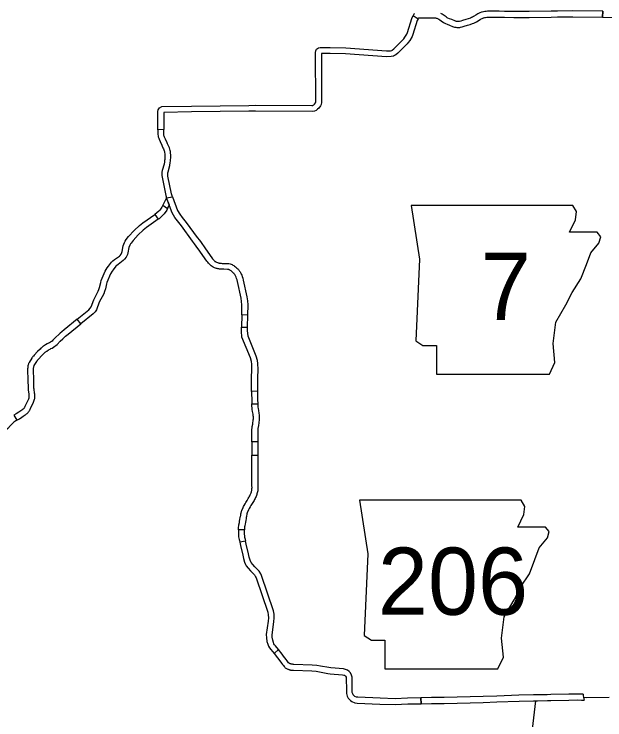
# Model space of a CAD drawing. Extents: x 77230 to 630905, y 790554 to 1662844.
# Drawn here: x 528426 to 553467, y 1510846 to 1540788 of the extents above; entities that cross this region are included whole.
import ezdxf

# ---------------------------------------------------------------- set-up
doc = ezdxf.new("R2010")
doc.units = 0
for name, color, linetype in [('Level 10', 7, 'Continuous'), ('Level 24', 7, 'Continuous'), ('Level 41', 7, 'Continuous')]:
    doc.layers.add(name, color=color, linetype=linetype)

msp = doc.modelspace()

# ---------------------------------------------------------------- linework, layer by layer
at = {"layer": 'Level 10'}
msp.add_line((539787, 1513639), (539632, 1513831), dxfattribs=at)
for points in [[(553376, 1540913), (553372, 1540663), (554654, 1540645), (556930, 1540667), (557078, 1540724), (557133, 1540754), (557189, 1540803), (557224, 1540843), (557250, 1540888), (557277, 1540964), (557289, 1541026), (557309, 1542253), (557309, 1543120), (557302, 1543626), (557052, 1543626)], [(553372, 1540663), (553376, 1540913), (552103, 1540922), (551457, 1540919), (551188, 1540910), (550258, 1540897), (549906, 1540893), (549617, 1540893), (549218, 1540903), (548984, 1540910), (548632, 1540915), (548564, 1540912), (548490, 1540910), (548431, 1540904), (548373, 1540897), (548323, 1540887), (548271, 1540873), (548244, 1540864), (548171, 1540837), (548084, 1540796)], [(541203, 1539162), (541211, 1539234), (541250, 1539306), (541325, 1539357), (541399, 1539373), (541824, 1539373), (542485, 1539357), (544207, 1539225), (544379, 1539234), (544430, 1539246), (544432, 1539246), (544457, 1539264), (544520, 1539318), (544840, 1539641), (544902, 1539699), (544940, 1539741), (544990, 1539807), (545067, 1539942), (545095, 1540011), (545282, 1540609), (545341, 1540734), (545549, 1540595)], [(545549, 1540595), (545516, 1540520), (545330, 1539928), (545293, 1539834), (545199, 1539669), (545134, 1539582), (545081, 1539523), (545014, 1539461), (544690, 1539134), (544610, 1539065), (544552, 1539026), (544507, 1539007), (544413, 1538985), (544204, 1538975), (542473, 1539107), (541821, 1539123), (541449, 1539123)], [(545391, 1540801), (545374, 1540780), (545359, 1540762), (545341, 1540734), (545549, 1540595)], [(545549, 1540595), (545563, 1540616), (545569, 1540624), (545572, 1540628), (545574, 1540630), (545580, 1540635), (545581, 1540635), (545605, 1540636), (545679, 1540636), (546249, 1540630), (546284, 1540628), (546313, 1540623), (546344, 1540617), (546367, 1540609), (546402, 1540592), (546435, 1540574), (546471, 1540551), (546590, 1540465), (546617, 1540446), (546659, 1540420), (546710, 1540393), (546782, 1540363), (546885, 1540323), (547011, 1540267), (547048, 1540253), (547090, 1540239), (547145, 1540228), (547194, 1540223), (547238, 1540221), (547280, 1540221), (547316, 1540225), (547354, 1540232), (547424, 1540250), (547500, 1540271), (547648, 1540317), (547754, 1540353), (547854, 1540388), (547907, 1540408), (547966, 1540434), (548028, 1540466), (548134, 1540535), (548201, 1540575)], [(548084, 1540796), (548003, 1540747), (547901, 1540682), (547859, 1540660), (547812, 1540640), (547767, 1540622), (547673, 1540589), (547571, 1540555), (547429, 1540511), (547359, 1540491), (547302, 1540476), (547280, 1540473), (547265, 1540471), (547245, 1540471), (547213, 1540473), (547182, 1540476), (547153, 1540482), (547132, 1540488), (547106, 1540498), (546981, 1540553), (546876, 1540595), (546815, 1540620), (546783, 1540637), (546757, 1540653), (546735, 1540669), (546611, 1540758), (546564, 1540788), (546517, 1540814)], [(548201, 1540575), (548268, 1540606), (548327, 1540628), (548343, 1540633), (548381, 1540644), (548413, 1540650), (548457, 1540656), (548506, 1540660), (548573, 1540662), (548635, 1540665), (548979, 1540660), (549212, 1540653), (549614, 1540643), (549907, 1540643), (550261, 1540647), (551193, 1540660), (551462, 1540669), (552103, 1540672), (553372, 1540663)], [(534770, 1535886), (534520, 1535885), (534517, 1536659), (534537, 1536728), (534589, 1536818), (534685, 1536863), (535942, 1536889), (538371, 1536916), (538658, 1536925), (541043, 1536909), (541082, 1536916), (541103, 1536924), (541131, 1536945), (541162, 1536972), (541203, 1537026), (541204, 1537028), (541208, 1537053), (541199, 1539117), (541203, 1539162)], [(541449, 1539123), (541458, 1537032), (541444, 1536950), (541417, 1536894), (541347, 1536803), (541288, 1536749), (541223, 1536704), (541152, 1536675), (541064, 1536659), (538661, 1536675), (538376, 1536667), (535946, 1536639), (534767, 1536614), (534770, 1535886)], [(534770, 1535886), (534520, 1535885), (534520, 1535685), (534525, 1535629), (534536, 1535577), (534553, 1535525), (534572, 1535479), (534612, 1535385), (534683, 1535226), (534705, 1535179), (534735, 1535121), (534757, 1535072), (534774, 1535026), (534789, 1534984), (534798, 1534954), (534804, 1534917), (534810, 1534866), (534813, 1534815), (534813, 1534699), (534810, 1534623), (534805, 1534572), (534799, 1534517)], [(535047, 1534489), (535054, 1534546), (535060, 1534606), (535063, 1534695), (535063, 1534821), (535060, 1534887), (535052, 1534954), (535042, 1535009), (535028, 1535059), (535009, 1535112), (534988, 1535169), (534960, 1535230), (534929, 1535291), (534909, 1535331), (534841, 1535484), (534803, 1535574), (534788, 1535611), (534778, 1535643), (534772, 1535666), (534770, 1535696), (534770, 1535886)], [(534799, 1534517), (534784, 1534418), (534706, 1534149), (534693, 1534087), (534690, 1533947), (534701, 1533867), (534851, 1533090), (534886, 1532995), (535139, 1533031)], [(535139, 1533031), (535092, 1533157), (534948, 1533908), (534940, 1533961), (534943, 1534059), (534949, 1534090), (535028, 1534365), (535047, 1534489)], [(534886, 1532995), (534724, 1532678), (534932, 1532536)], [(535990, 1531162), (535515, 1531801), (535346, 1532015), (535240, 1532161), (535131, 1532354), (534886, 1532995), (535139, 1533031)], [(534932, 1532536), (535006, 1532681), (534886, 1532995)], [(535139, 1533031), (535358, 1532461), (535451, 1532296), (535545, 1532165), (535713, 1531953), (536190, 1531312)], [(534724, 1532678), (534684, 1532599), (534596, 1532475), (534557, 1532433), (534392, 1532291)], [(534932, 1532536), (534898, 1532470), (534791, 1532318), (534733, 1532255), (534568, 1532108), (534532, 1532084)], [(531256, 1527652), (531100, 1527847), (531599, 1528246), (531653, 1528310), (531688, 1528364), (531808, 1528667), (531994, 1529031), (532021, 1529098), (532050, 1529194), (532096, 1529404), (532121, 1529482), (532288, 1529889), (532370, 1530020), (532422, 1530093), (532556, 1530262), (532609, 1530315), (532681, 1530372), (532891, 1530522), (532917, 1530548), (532960, 1530607), (532976, 1530636), (532989, 1530669), (533003, 1530720), (533050, 1530958), (533104, 1531093), (533137, 1531158), (533176, 1531221), (533280, 1531351), (533511, 1531602), (533737, 1531815), (533885, 1531935), (534392, 1532291), (534532, 1532084)], [(534532, 1532084), (534036, 1531735), (533902, 1531627), (533690, 1531426), (533470, 1531187), (533380, 1531076), (533355, 1531036), (533333, 1530991), (533291, 1530887), (533246, 1530663), (533227, 1530591), (533203, 1530528), (533170, 1530471), (533108, 1530386), (533054, 1530332), (532831, 1530172), (532776, 1530128), (532743, 1530095), (532622, 1529942), (532578, 1529881), (532512, 1529775), (532356, 1529396), (532338, 1529339), (532292, 1529131), (532258, 1529016), (532222, 1528927), (532036, 1528563), (531911, 1528249), (531854, 1528161), (531774, 1528066), (531256, 1527652)], [(536190, 1531312), (536278, 1531194), (536351, 1531092), (536504, 1530875), (536636, 1530688), (536803, 1530454), (536833, 1530412), (536856, 1530384), (536887, 1530349), (536919, 1530316), (536938, 1530299), (536955, 1530287), (536975, 1530277), (537010, 1530262), (537048, 1530249), (537075, 1530240), (537098, 1530234), (537119, 1530229), (537138, 1530226), (537157, 1530223), (537197, 1530220), (537247, 1530215), (537329, 1530212), (537482, 1530207), (537529, 1530203), (537580, 1530194), (537624, 1530180), (537668, 1530161), (537700, 1530143), (537734, 1530121), (537771, 1530095), (537807, 1530069), (537842, 1530039), (537871, 1530011), (537904, 1529982), (537935, 1529950), (537952, 1529930), (537969, 1529908), (537986, 1529883), (538009, 1529848), (538035, 1529803), (538055, 1529760), (538075, 1529710), (538095, 1529652), (538118, 1529579), (538138, 1529506)], [(537896, 1529440), (537877, 1529510), (537858, 1529575), (537841, 1529623), (537826, 1529660), (537814, 1529686), (537796, 1529717), (537779, 1529744), (537768, 1529759), (537758, 1529772), (537749, 1529782), (537729, 1529803), (537702, 1529828), (537675, 1529852), (537652, 1529872), (537625, 1529892), (537595, 1529913), (537571, 1529928), (537555, 1529938), (537536, 1529946), (537522, 1529950), (537496, 1529955), (537466, 1529957), (537320, 1529962), (537231, 1529966), (537175, 1529971), (537131, 1529974), (537098, 1529979), (537067, 1529985), (537038, 1529991), (537006, 1530000), (536968, 1530011), (536920, 1530029), (536868, 1530051), (536825, 1530074), (536782, 1530103), (536746, 1530136), (536705, 1530178), (536666, 1530221), (536635, 1530260), (536600, 1530308), (536432, 1530544), (536300, 1530731), (536147, 1530947), (536076, 1531047), (535990, 1531162)], [(538138, 1529506), (538292, 1528787), (538318, 1528623), (538333, 1528461), (538322, 1528019)], [(538322, 1528019), (538072, 1528024), (538082, 1528453), (538070, 1528592), (538046, 1528740), (537896, 1529440)], [(538072, 1528024), (538061, 1527507)], [(538322, 1528019), (538310, 1527501)], [(531256, 1527652), (531100, 1527847), (530553, 1527399), (530450, 1527315), (530374, 1527250), (530317, 1527198), (530198, 1527082), (530073, 1526953), (530036, 1526920), (530003, 1526892), (529968, 1526868), (529930, 1526846), (529881, 1526825), (529824, 1526796), (529754, 1526751), (529676, 1526702), (529645, 1526683), (529610, 1526657), (529582, 1526634), (529551, 1526609), (529523, 1526580), (529423, 1526477), (529278, 1526314), (529244, 1526279), (529223, 1526258), (529208, 1526239), (529192, 1526217), (529181, 1526199), (529172, 1526185), (529060, 1526008), (529049, 1525985), (529039, 1525960), (529031, 1525937), (529022, 1525906), (529013, 1525867), (529006, 1525827), (529000, 1525785), (528995, 1525735), (529007, 1525236), (529014, 1524962), (529018, 1524903), (529022, 1524850), (529047, 1524670), (529051, 1524638), (529054, 1524611), (529056, 1524576), (529056, 1524555), (529055, 1524539), (529053, 1524529), (529049, 1524512), (529043, 1524492), (529031, 1524457), (529017, 1524425), (528898, 1524166), (528885, 1524139), (528866, 1524102), (528858, 1524086), (528852, 1524077), (528846, 1524068), (528837, 1524057), (528831, 1524052), (528823, 1524044), (528812, 1524035), (528799, 1524024), (528776, 1524007), (528750, 1523988), (528673, 1523934), (528619, 1523898), (528518, 1523834), (528412, 1523768), (528544, 1523556)], [(528544, 1523556), (528651, 1523622), (528756, 1523689), (528814, 1523728), (528895, 1523785), (528924, 1523806), (528952, 1523826), (528973, 1523843), (528991, 1523859), (529005, 1523873), (529020, 1523887), (529041, 1523911), (529061, 1523938), (529077, 1523966), (529089, 1523989), (529108, 1524026), (529124, 1524058), (529246, 1524325), (529264, 1524368), (529281, 1524416), (529290, 1524446), (529297, 1524476), (529303, 1524507), (529306, 1524548), (529305, 1524586), (529303, 1524630), (529299, 1524666), (529295, 1524703), (529271, 1524875), (529268, 1524919), (529264, 1524973), (529257, 1525242), (529246, 1525726), (529249, 1525756), (529253, 1525788), (529258, 1525817), (529264, 1525842), (529270, 1525862), (529274, 1525875), (529278, 1525884), (529278, 1525885), (529383, 1526051), (529393, 1526067), (529400, 1526079), (529405, 1526085), (529411, 1526092), (529423, 1526105), (529460, 1526143), (529606, 1526307), (529701, 1526405), (529720, 1526424), (529741, 1526441), (529764, 1526460), (529785, 1526476), (529808, 1526490), (529889, 1526540), (529948, 1526579), (529987, 1526599), (530040, 1526622), (530100, 1526655), (530156, 1526694), (530200, 1526731), (530247, 1526773), (530375, 1526906), (530489, 1527016), (530540, 1527063), (530610, 1527123), (530711, 1527205), (531256, 1527652)], [(538083, 1527082), (538057, 1527340), (538061, 1527507), (538310, 1527501)], [(538310, 1527501), (538307, 1527350), (538328, 1527143)], [(538501, 1525729), (538499, 1525934), (538482, 1526051), (538439, 1526203), (538083, 1527082)], [(538328, 1527143), (538676, 1526284), (538727, 1526102), (538748, 1525953), (538751, 1525732)], [(538744, 1524787), (538494, 1524783), (538494, 1524935), (538488, 1525078), (538494, 1525348), (538501, 1525729)], [(538751, 1525732), (538744, 1525343), (538738, 1525081), (538744, 1524940), (538744, 1524787)], [(538494, 1524783), (538494, 1524680), (538499, 1524436), (538504, 1524255)], [(538744, 1524787), (538744, 1524683), (538749, 1524442), (538754, 1524258)], [(538504, 1524255), (538754, 1524258), (538757, 1524169), (538761, 1524117), (538771, 1524051), (538784, 1523965), (538803, 1523860), (538814, 1523770), (538817, 1523707), (538817, 1523644), (538815, 1523598), (538811, 1523548), (538805, 1523490), (538798, 1523429), (538784, 1523345), (538766, 1523247), (538761, 1523216), (538755, 1523140), (538754, 1523069), (538754, 1522645)], [(538754, 1522645), (538504, 1522643), (538504, 1523070), (538505, 1523152), (538513, 1523244), (538519, 1523287), (538538, 1523389), (538551, 1523465), (538557, 1523516), (538562, 1523570), (538566, 1523615), (538567, 1523649), (538567, 1523701), (538565, 1523749), (538556, 1523822), (538537, 1523923), (538523, 1524013), (538512, 1524089), (538507, 1524156), (538504, 1524255)], [(528412, 1523768), (528544, 1523556), (528420, 1523471), (528392, 1523451), (528372, 1523436), (528352, 1523419), (528325, 1523391), (528275, 1523338), (528153, 1523206), (528123, 1523173), (527885, 1522896), (527823, 1522826)], [(538504, 1522643), (538504, 1522137), (538504, 1522078)], [(538754, 1522645), (538754, 1522137), (538754, 1522081)], [(538470, 1520484), (538482, 1520519), (538490, 1520547), (538497, 1520574), (538503, 1520601), (538506, 1520627), (538508, 1520662), (538510, 1520703), (538509, 1520778), (538504, 1521116), (538504, 1522078)], [(538504, 1522078), (538754, 1522081), (538754, 1521118), (538759, 1520781), (538760, 1520696), (538757, 1520648), (538755, 1520607), (538750, 1520561), (538740, 1520517), (538731, 1520481), (538720, 1520442), (538707, 1520405)], [(538185, 1518913), (537935, 1518915), (537937, 1518967), (537940, 1519025), (537946, 1519077), (537956, 1519128), (537978, 1519221), (537986, 1519266), (537999, 1519356), (538010, 1519424), (538023, 1519490), (538030, 1519517), (538034, 1519544), (538041, 1519598), (538044, 1519622), (538050, 1519647), (538058, 1519674), (538065, 1519694), (538076, 1519725), (538130, 1519861), (538154, 1519905), (538172, 1519935), (538220, 1520016), (538249, 1520067), (538304, 1520155), (538353, 1520235), (538378, 1520279), (538392, 1520306), (538418, 1520355), (538435, 1520389), (538447, 1520417), (538457, 1520445), (538470, 1520484)], [(538707, 1520405), (538694, 1520364), (538679, 1520323), (538661, 1520283), (538641, 1520242), (538614, 1520191), (538597, 1520158), (538567, 1520107), (538517, 1520024), (538464, 1519938), (538436, 1519889), (538387, 1519807), (538372, 1519782), (538357, 1519755), (538309, 1519636), (538301, 1519612), (538296, 1519599), (538292, 1519584), (538291, 1519578), (538289, 1519566), (538282, 1519509), (538275, 1519468), (538268, 1519437), (538256, 1519378), (538246, 1519318), (538233, 1519226), (538222, 1519169), (538200, 1519076), (538193, 1519039), (538189, 1519003), (538186, 1518956), (538185, 1518913)], [(537935, 1518915), (537930, 1518801), (537930, 1518742), (537933, 1518699), (537936, 1518659), (537942, 1518606), (537953, 1518550), (537963, 1518501), (537973, 1518454), (537989, 1518391)], [(538185, 1518913), (538184, 1518883), (538180, 1518795), (538180, 1518751), (538182, 1518717), (538185, 1518683), (538189, 1518644), (538198, 1518598), (538207, 1518553), (538216, 1518511), (538237, 1518423)], [(538235, 1518423), (537989, 1518391), (538025, 1518246), (538121, 1517829)], [(538363, 1517884), (538267, 1518305), (538235, 1518423)], [(538121, 1517829), (538149, 1517692), (538194, 1517539), (538236, 1517443), (538268, 1517388), (538345, 1517281), (538442, 1517170), (538614, 1516997), (538664, 1516920), (538687, 1516873), (539183, 1515417), (539201, 1515307), (539203, 1515179), (539188, 1515033), (539116, 1514465), (539118, 1514328), (539143, 1514177), (539181, 1514053), (539214, 1513968), (539250, 1513902), (539302, 1513827), (539444, 1513666), (539632, 1513831)], [(539632, 1513831), (539499, 1513982), (539463, 1514034), (539441, 1514074), (539417, 1514135), (539387, 1514234), (539368, 1514350), (539366, 1514451), (539437, 1515006), (539453, 1515169), (539451, 1515329), (539427, 1515478), (538918, 1516970), (538881, 1517044), (538809, 1517155), (538625, 1517341), (538541, 1517436), (538478, 1517525), (538459, 1517557), (538429, 1517624), (538392, 1517753), (538363, 1517884)], [(539632, 1513831), (539444, 1513666), (539593, 1513481)], [(540277, 1513201), (540250, 1513202), (540231, 1513203), (540212, 1513204), (540200, 1513205), (540189, 1513207), (540181, 1513209), (540171, 1513211), (540165, 1513214), (540155, 1513217), (540143, 1513222), (540130, 1513228), (540113, 1513236), (540098, 1513244), (540084, 1513253), (540075, 1513259), (540071, 1513263), (540063, 1513271), (540032, 1513307), (539996, 1513352), (539959, 1513401), (539848, 1513551), (539787, 1513639)], [(539593, 1513481), (539645, 1513405), (539759, 1513251), (539799, 1513198), (539840, 1513147), (539877, 1513104), (539897, 1513082), (539922, 1513061), (539947, 1513044), (539970, 1513029), (539997, 1513014), (540024, 1513001), (540044, 1512992), (540066, 1512983), (540083, 1512977), (540099, 1512972), (540121, 1512966), (540142, 1512961), (540168, 1512957), (540195, 1512954), (540220, 1512953), (540239, 1512952), (540268, 1512951)], [(544579, 1511743), (543939, 1511762), (542995, 1511803), (542939, 1511815), (542869, 1511845), (542844, 1511862), (542819, 1511883), (542798, 1511908), (542778, 1511946), (542760, 1512005), (542762, 1512087), (542751, 1512656), (542733, 1512737), (542683, 1512841), (542635, 1512893), (542556, 1512957), (542479, 1512987), (542385, 1513005), (541853, 1513049), (541769, 1513062), (541418, 1513130), (541255, 1513156), (541065, 1513174), (540277, 1513201)], [(540268, 1512951), (541050, 1512924), (541224, 1512908), (541374, 1512884), (541727, 1512815), (541825, 1512801), (542351, 1512757), (542408, 1512746), (542428, 1512739), (542464, 1512710), (542474, 1512699), (542495, 1512655), (542501, 1512626), (542512, 1512087), (542510, 1511971), (542546, 1511851), (542590, 1511767), (542641, 1511707), (542691, 1511664), (542748, 1511624), (542865, 1511575), (542963, 1511554), (543930, 1511513), (544572, 1511493)], [(552543, 1511935), (552314, 1511942), (551938, 1511932), (551176, 1511918), (551025, 1511913), (550615, 1511908), (550444, 1511908), (549820, 1511893), (548885, 1511856), (548307, 1511836), (546651, 1511798), (546120, 1511796), (545669, 1511781), (545678, 1511531)], [(552559, 1511808), (552697, 1511801)], [(552697, 1511801), (553647, 1511815)], [(544572, 1511493), (545110, 1511521), (545676, 1511531)], [(545676, 1511531), (545671, 1511781), (545101, 1511771), (544579, 1511743)], [(545678, 1511531), (546125, 1511546), (546654, 1511548), (548314, 1511586), (548894, 1511606), (549828, 1511643), (550447, 1511658), (550617, 1511658), (551030, 1511663), (551182, 1511668), (551943, 1511682), (552314, 1511692), (552480, 1511687), (552583, 1511682)]]:
    msp.add_lwpolyline(points, dxfattribs=at)
msp.add_arc((554369, 1512098), 1833, 185.1008, 193.1354, dxfattribs=at)
at = {"layer": 'Level 24'}
for points in [[(545261, 1532674), (545604, 1530391), (545451, 1526927), (545756, 1526736), (546327, 1526736), (546327, 1525518), (551123, 1525518), (551351, 1526013), (551275, 1526812), (551390, 1527726), (551808, 1528449), (552075, 1528982), (552455, 1529553), (552684, 1530162), (552874, 1530657), (553217, 1531076), (553293, 1531342), (553141, 1531533), (551961, 1531533), (552227, 1532065), (552265, 1532408), (552107, 1532671)], [(545261, 1532674), (545604, 1530391), (545451, 1526927), (545756, 1526736), (546327, 1526736), (546327, 1525518), (551123, 1525518), (551351, 1526013), (551275, 1526812), (551390, 1527726), (551808, 1528449), (552075, 1528982), (552455, 1529553), (552684, 1530162), (552874, 1530657), (553217, 1531076), (553293, 1531342), (553141, 1531533), (551961, 1531533), (552227, 1532065), (552265, 1532408), (552107, 1532671)], [(543073, 1520168), (543416, 1517884), (543263, 1514420), (543568, 1514230), (544139, 1514230), (544139, 1513012), (548935, 1513012), (549164, 1513507), (549087, 1514306), (549202, 1515220), (549620, 1515943), (549887, 1516476), (550267, 1517047), (550496, 1517656), (550686, 1518151), (551029, 1518569), (551105, 1518836), (550953, 1519026), (549773, 1519026), (550039, 1519559), (550077, 1519902), (549919, 1520165)], [(543073, 1520168), (543416, 1517884), (543263, 1514420), (543568, 1514230), (544139, 1514230), (544139, 1513012), (548935, 1513012), (549164, 1513507), (549087, 1514306), (549202, 1515220), (549620, 1515943), (549887, 1516476), (550267, 1517047), (550496, 1517656), (550686, 1518151), (551029, 1518569), (551105, 1518836), (550953, 1519026), (549773, 1519026), (550039, 1519559), (550077, 1519902), (549919, 1520165)]]:
    msp.add_lwpolyline(points, close=True, dxfattribs=at)
at = {"layer": 'Level 41'}
msp.add_lwpolyline([(550532, 1511658), (546688, 1478945), (558497, 1512665)], dxfattribs=at)

# ---------------------------------------------------------------- texts
at = {"layer": 'Level 24'}
for s, height, p in [('7', 2851, (548207, 1527810)), ('7', 2851, (548207, 1527810)), ('206', 2851.2, (543849, 1515304)), ('206', 2851.2, (543849, 1515304))]:
    msp.add_text(s, height=height, dxfattribs=at).set_placement(p)

doc.saveas('drawing.dxf')
